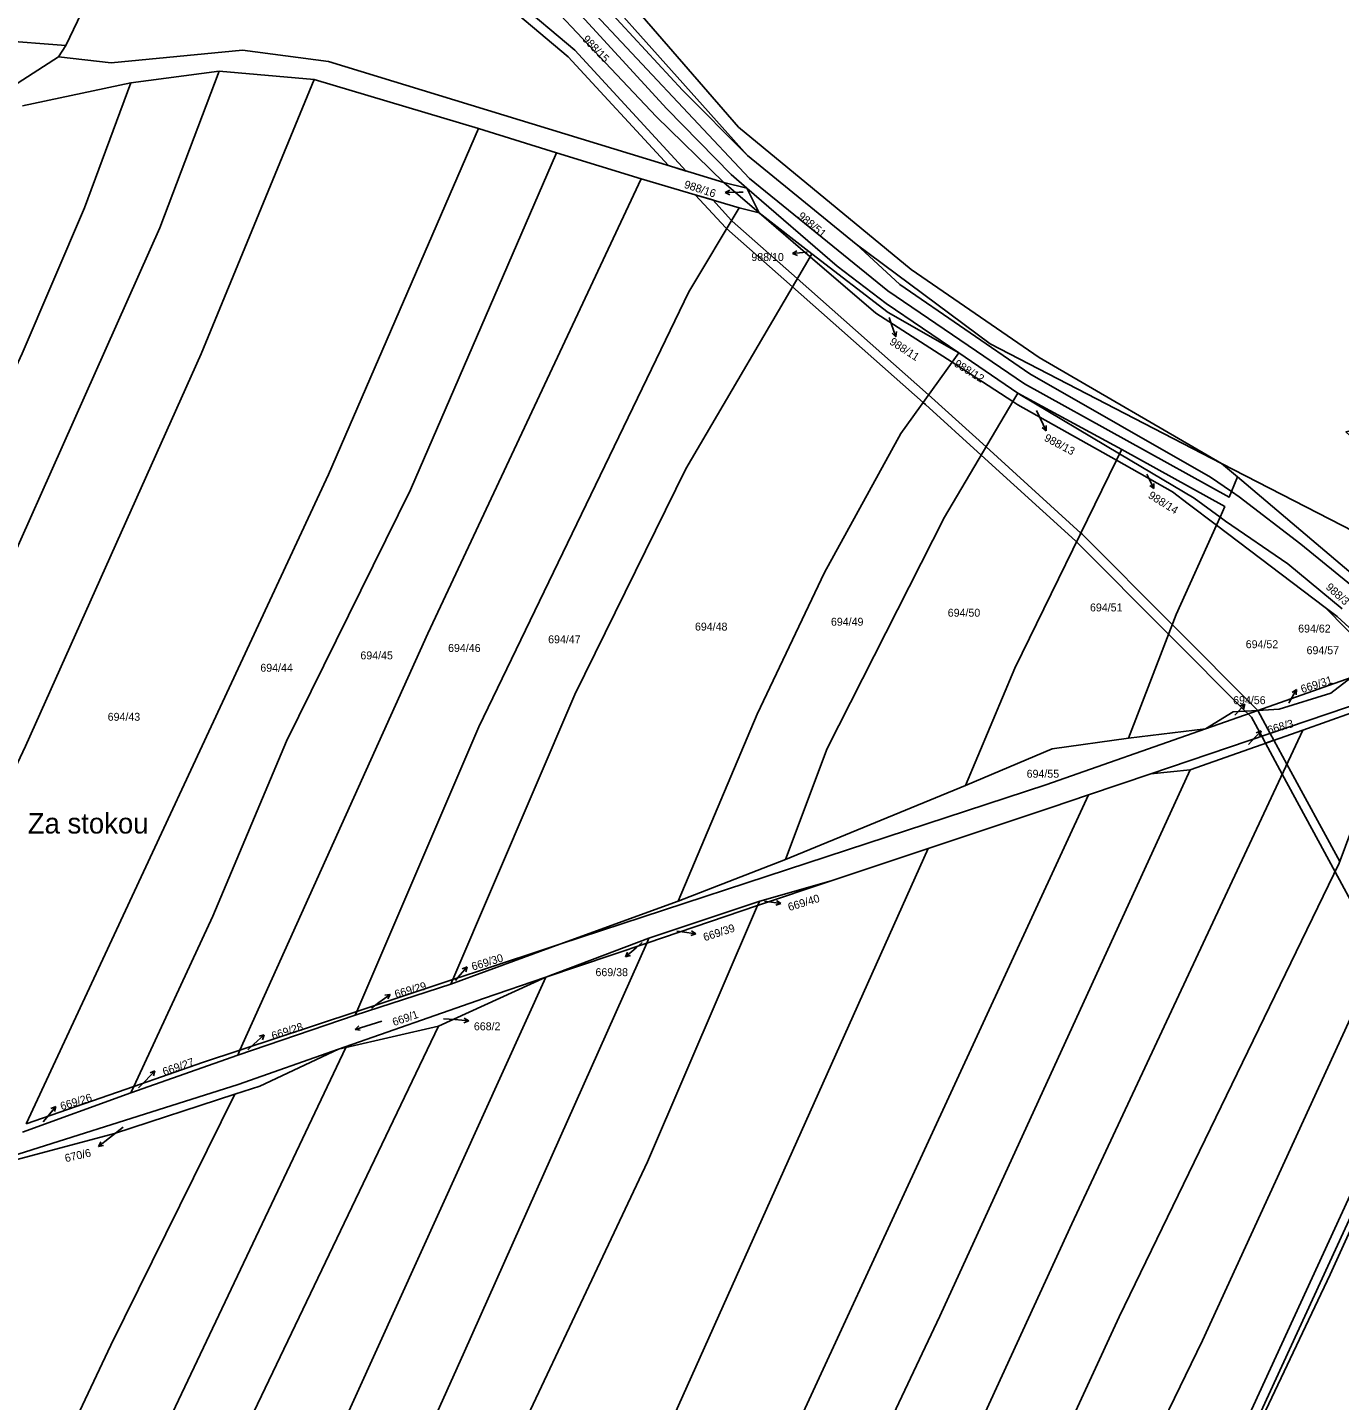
# Model space of a CAD drawing. Extents: x -757266 to -753360, y -1162585 to -1157740.
# Drawn here: x -755234 to -754953.1, y -1160665.3 to -1160371.4 of the extents above; entities that cross this region are included whole.
import ezdxf

# ---------------------------------------------------------------- set-up
doc = ezdxf.new("R2010")
doc.units = 0
for name, color, linetype in [('Hranice kat_území', 7, 'Continuous'), ('Hranice parcel', 7, 'Continuous'), ('Parcelní čísla', 7, 'Continuous'), ('Pop  PČ popisy', 7, 'Continuous'), ('Vnitřní kresba', 7, 'Continuous'), ('Věcná břemena k části', 7, 'Continuous'), ('Značky kultur', 7, 'Continuous')]:
    doc.layers.add(name, color=color, linetype=linetype)

msp = doc.modelspace()

# ---------------------------------------------------------------- linework, layer by layer
at = {"layer": 'Hranice kat_území'}
msp.add_lwpolyline([(-754836.68, -1160424.92), (-754843.51, -1160426.34), (-754867.82, -1160439.33), (-754951.71, -1160457.97), (-754910, -1160495.94), (-754907.43, -1160498.28), (-754905.04, -1160500.46), (-754900.14, -1160504.92), (-754937.1, -1160485.93), (-754978.36, -1160464.73), (-755017.36, -1160442.06), (-755044.83, -1160423.21), (-755081.79, -1160392.71), (-755127.23, -1160340.27), (-755153.29, -1160310.66), (-755189.84, -1160272.57)], dxfattribs=at)
at = {"layer": 'Hranice parcel'}
for p, q in [((-755225.78, -1160375.24), (-755214.23, -1160351.12)), ((-755225.78, -1160375.24), (-755408.03, -1160361.2)), ((-755227.31, -1160377.66), (-755225.78, -1160375.24)), ((-755192.92, -1160380.76), (-755211.82, -1160383.2)), ((-755172.6, -1160382.49), (-755192.92, -1160380.76)), ((-755211.82, -1160383.2), (-755235.06, -1160388.17)), ((-755137.45, -1160392.98), (-755172.6, -1160382.49)), ((-755120.74, -1160398.19), (-755137.45, -1160392.98)), ((-755102.58, -1160403.76), (-755120.74, -1160398.19)), ((-755079.81, -1160398.79), (-755056.55, -1160417.74)), ((-755081.62, -1160409.96), (-755102.58, -1160403.76)), ((-755084.87, -1160404.6), (-755079.94, -1160405.8)), ((-755084.87, -1160404.6), (-755077.36, -1160411.06)), ((-755077.36, -1160411.06), (-755079.94, -1160405.8)), ((-755077.36, -1160411.06), (-755081.62, -1160409.96)), ((-755077.36, -1160411.06), (-755066.09, -1160419.85)), ((-755066.44, -1160420.45), (-755077.36, -1160411.06)), ((-755066.44, -1160420.45), (-755066.09, -1160419.85)), ((-755034.6, -1160441.06), (-755036.04, -1160443.06)), ((-755021.95, -1160449.65), (-755034.6, -1160441.06)), ((-755036.04, -1160443.06), (-755023.01, -1160451.44)), ((-755023.01, -1160451.44), (-755021.95, -1160449.65)), ((-755021.95, -1160449.65), (-754999.73, -1160461.76)), ((-754978.36, -1160464.73), (-754974.95, -1160467.61)), ((-754979.45, -1160477.93), (-754956.2, -1160495.52)), ((-754947.13, -1160504.73), (-754956.2, -1160495.52)), ((-754950.61, -1160510.55), (-754970.61, -1160517.59)), ((-754947.42, -1160515.55), (-754993.5, -1160531.15)), ((-754970.61, -1160517.59), (-754981.79, -1160521.52)), ((-754998.29, -1160523.54), (-754981.79, -1160521.52)), ((-754985.1, -1160530.3), (-754960.96, -1160521.81)), ((-754993.5, -1160531.15), (-754985.1, -1160530.3)), ((-755071.71, -1160549.47), (-755033.18, -1160533.67)), ((-754993.5, -1160531.15), (-755006.85, -1160535.67)), ((-755041.15, -1160547.16), (-755061.89, -1160554.09)), ((-755094.69, -1160558.4), (-755071.71, -1160549.47)), ((-755061.89, -1160554.09), (-755077.67, -1160559.36)), ((-755077.16, -1160558.43), (-755061.89, -1160554.09)), ((-755120, -1160567.65), (-755094.69, -1160558.4)), ((-755077.67, -1160559.36), (-755101.37, -1160567.38)), ((-755100.92, -1160566.36), (-755077.16, -1160558.43)), ((-755077.67, -1160559.36), (-755077.16, -1160558.43)), ((-755120, -1160567.65), (-755143.33, -1160576.17)), ((-755123.03, -1160574.7), (-755100.92, -1160566.36)), ((-755101.37, -1160567.38), (-755123.03, -1160574.7)), ((-755101.37, -1160567.38), (-755100.92, -1160566.36)), ((-755146, -1160585.19), (-755123.03, -1160574.7)), ((-755143.33, -1160576.17), (-755163.81, -1160582.84)), ((-755142.91, -1160575.19), (-755163.45, -1160582.01)), ((-755143.33, -1160576.17), (-755142.91, -1160575.19)), ((-755163.81, -1160582.84), (-755188.97, -1160591.37)), ((-755163.45, -1160582.01), (-755188.5, -1160590.32)), ((-755163.81, -1160582.84), (-755163.45, -1160582.01)), ((-755165.8, -1160589.74), (-755146, -1160585.19)), ((-755167.41, -1160590.11), (-755165.8, -1160589.74)), ((-755188.97, -1160591.37), (-755211.87, -1160599.47)), ((-755188.97, -1160591.37), (-755188.5, -1160590.32)), ((-755211.23, -1160598.09), (-755234.24, -1160606.08)), ((-755211.87, -1160599.47), (-755211.23, -1160598.09)), ((-755211.87, -1160599.47), (-755235.07, -1160607.86))]:
    msp.add_line(p, q, dxfattribs=at)
for points in [[(-754978.36, -1160464.73), (-755017.36, -1160442.06), (-755044.83, -1160423.21), (-755081.79, -1160392.71), (-755127.23, -1160340.27), (-755153.29, -1160310.66), (-755189.84, -1160272.57), (-755198.61, -1160264.22)], [(-755179.02, -1160301.66), (-755140.77, -1160333.66), (-755129.85, -1160342.79), (-755079.81, -1160398.79)], [(-754974.95, -1160467.61), (-754976.22, -1160470.75), (-754976.7, -1160471.93), (-755020.51, -1160447.64), (-755049.76, -1160427.78), (-755079.39, -1160403.71), (-755139.72, -1160339.43), (-755150.98, -1160330.64), (-755160.64, -1160323.09)], [(-755079.94, -1160405.8), (-755083.32, -1160402.88), (-755097.07, -1160388.79), (-755134.5, -1160347.95), (-755136.84, -1160350.67)], [(-755136.84, -1160350.67), (-755099.4, -1160390.46), (-755084.87, -1160404.6)], [(-755408.03, -1160361.2), (-755410.88, -1160362.74), (-755447.95, -1160377.88), (-755452.11, -1160383.8), (-755423.38, -1160389.29), (-755390.71, -1160391.7), (-755352.32, -1160391.92), (-755317.01, -1160388.19), (-755277.97, -1160387.97), (-755237.18, -1160384.02), (-755227.31, -1160377.66)], [(-755227.31, -1160377.66), (-755216.08, -1160378.97), (-755187.92, -1160376.23), (-755169.51, -1160378.66), (-755084.87, -1160404.6)], [(-755302.8, -1160627.98), (-755258.75, -1160533.19), (-755205.63, -1160414.29), (-755192.92, -1160380.76)], [(-755322.45, -1160633.68), (-755269.46, -1160515.52), (-755235.11, -1160441.19), (-755221.8, -1160410.02), (-755211.82, -1160383.2)], [(-755279.36, -1160620.71), (-755234.42, -1160525.24), (-755196.79, -1160441.23), (-755172.6, -1160382.49)], [(-755234.24, -1160606.08), (-755169.52, -1160467.09), (-755137.45, -1160392.98)], [(-755211.23, -1160598.09), (-755194.26, -1160561.64), (-755178.49, -1160524.16), (-755152.01, -1160470.33), (-755120.74, -1160398.19)], [(-755188.5, -1160590.32), (-755148.28, -1160501.09), (-755102.58, -1160403.76)], [(-755163.45, -1160582.01), (-755137.33, -1160521.1), (-755092.39, -1160427.99), (-755081.62, -1160409.96)], [(-755056.55, -1160417.74), (-755027.91, -1160439.08), (-754978.36, -1160464.73)], [(-755142.91, -1160575.19), (-755116.78, -1160514.16), (-755093.04, -1160465.87), (-755066.44, -1160420.45)], [(-755036.04, -1160443.06), (-755052.36, -1160432.55), (-755066.44, -1160420.45)], [(-755066.09, -1160419.85), (-755049.71, -1160432.37), (-755034.6, -1160441.06)], [(-755094.69, -1160558.4), (-755077.77, -1160518.41), (-755063.34, -1160488.04), (-755047.02, -1160458.28), (-755036.04, -1160443.06)], [(-755071.71, -1160549.47), (-755062.75, -1160525.7), (-755037.69, -1160476.19), (-755023.01, -1160451.44)], [(-755000.84, -1160464.02), (-755021.93, -1160452.14), (-755023.01, -1160451.44)], [(-755000.84, -1160464.02), (-755000.17, -1160462.65), (-754999.73, -1160461.76)], [(-754999.73, -1160461.76), (-754977.67, -1160473.96), (-754978.66, -1160476.18), (-754979.45, -1160477.93)], [(-755033.18, -1160533.67), (-755022.57, -1160508.57), (-755000.84, -1160464.02)], [(-754979.45, -1160477.93), (-754985.47, -1160473.37), (-754988.88, -1160470.76), (-755000.84, -1160464.02)], [(-754978.36, -1160464.73), (-754937.1, -1160485.93), (-754900.14, -1160504.92)], [(-754915.94, -1160516.47), (-754933.41, -1160503.58), (-754939.41, -1160497.69), (-754974.95, -1160467.61)], [(-754998.29, -1160523.54), (-754988.03, -1160497.04), (-754979.45, -1160477.93)], [(-754956.2, -1160495.52), (-754953.61, -1160497.48), (-754946.67, -1160503.85)], [(-755239.59, -1161188.33), (-755189.22, -1161066.1), (-755124.51, -1160919.12), (-755055.31, -1160766.7), (-755000.26, -1160647.4), (-754953.16, -1160550.31), (-754939.15, -1160512.75)], [(-754950.61, -1160510.55), (-754954.92, -1160513.92), (-754966.03, -1160517.34), (-754970.61, -1160517.59)], [(-754960.96, -1160521.81), (-754950.51, -1160518.13), (-754947.42, -1160515.55)], [(-754981.79, -1160521.52), (-754975.86, -1160517.87), (-754970.61, -1160517.59)], [(-755258.72, -1161181.18), (-755209.68, -1161068.68), (-755144.04, -1160922.19), (-755126.15, -1160879.45), (-755010.42, -1160627.49), (-754960.96, -1160521.81)], [(-754981.79, -1160521.52), (-755015.96, -1160533.54), (-755075.64, -1160553.07), (-755120, -1160567.65)], [(-755033.18, -1160533.67), (-755014.63, -1160525.78), (-754998.29, -1160523.54)], [(-755275.71, -1161173.74), (-755223.74, -1161057.26), (-755180.23, -1160958.74), (-755117.97, -1160820.72), (-755099.93, -1160776.84), (-755038.69, -1160647.24), (-754985.1, -1160530.3)], [(-755223.83, -1161194.14), (-755155.09, -1161030.95), (-755113.4, -1160935.38), (-755035.3, -1160761.37), (-754982.41, -1160652.48), (-754927.53, -1160532.91)], [(-755292.32, -1161165.4), (-755230.27, -1161030.46), (-755190.55, -1160934.6), (-755105.63, -1160749.58), (-755006.85, -1160535.67)], [(-755006.85, -1160535.67), (-755014.8, -1160538.36), (-755041.15, -1160547.16)], [(-755315.27, -1161153.68), (-755261.54, -1161031.78), (-755192.14, -1160879.45), (-755179.27, -1160847.36), (-755151.78, -1160790.14), (-755102.03, -1160682.93), (-755041.15, -1160547.16)], [(-755338.88, -1161141.19), (-755323.15, -1161100.32), (-755246.88, -1160934.52), (-755180.17, -1160786.32), (-755141.87, -1160700.25), (-755101.27, -1160614.23), (-755077.67, -1160559.36)], [(-755206.94, -1161200.05), (-755159.46, -1161085.95), (-755113.5, -1160980.32), (-755087.61, -1160917.94), (-755037.27, -1160811.67), (-754955.13, -1160638.32), (-754918.81, -1160558.44)], [(-755354.3, -1161132.73), (-755324.81, -1161064.13), (-755286.33, -1160980.6), (-755237.8, -1160874.55), (-755191.07, -1160767.63), (-755140.44, -1160654.8), (-755101.37, -1160567.38)], [(-755120, -1160567.65), (-755137.66, -1160573.45), (-755142.91, -1160575.19)], [(-755369.72, -1161124.77), (-755347.72, -1161071.88), (-755254.08, -1160863.01), (-755172.9, -1160684.55), (-755123.03, -1160574.7)], [(-755123.03, -1160574.7), (-755136.32, -1160579.23), (-755167.41, -1160590.11)], [(-755386.21, -1161118.44), (-755354.46, -1161042.9), (-755317.33, -1160958.88), (-755238.34, -1160786.92), (-755185.55, -1160667.77), (-755146, -1160585.19)], [(-755401.23, -1161112.85), (-755369.98, -1161038.68), (-755317.2, -1160921.35), (-755260.72, -1160793.9), (-755215.57, -1160694.59), (-755165.8, -1160589.74)], [(-755317.46, -1160638.78), (-755250.21, -1160617.08), (-755188.9, -1160597.63), (-755167.41, -1160590.11)], [(-755188.5, -1160590.32), (-755196.47, -1160592.97), (-755211.23, -1160598.09)], [(-755167.41, -1160590.11), (-755184.25, -1160598), (-755189.61, -1160599.75)], [(-755419.99, -1161106.75), (-755378.63, -1161012.83), (-755329.09, -1160900.22), (-755295.38, -1160824.05), (-755243.53, -1160711.37), (-755216.16, -1160653.5), (-755189.61, -1160599.75)], [(-755189.61, -1160599.75), (-755215.32, -1160608.12), (-755237.57, -1160614.05)]]:
    msp.add_lwpolyline(points, dxfattribs=at)
at = {"layer": 'Pop  PČ popisy'}
for p, q in [((-755084.591, -1160406.702), (-755083.598, -1160406.184)), ((-755081.59, -1160406.65), (-755084.591, -1160406.702)), ((-755084.591, -1160406.702), (-755083.58, -1160407.186)), ((-755080.78, -1160406.64), (-755081.59, -1160406.65)), ((-755070.195, -1160419.774), (-755069.251, -1160419.171)), ((-755067.21, -1160419.46), (-755070.195, -1160419.774)), ((-755070.195, -1160419.774), (-755069.146, -1160420.167)), ((-755067.09, -1160419.45), (-755067.21, -1160419.46)), ((-755049.5, -1160433.47), (-755049.06, -1160434.77)), ((-755049.06, -1160434.77), (-755048.083, -1160437.607)), ((-755048.083, -1160437.607), (-755048.882, -1160436.824)), ((-755048.083, -1160437.607), (-755047.936, -1160436.498)), ((-755017.98, -1160453.39), (-755017.19, -1160455.03)), ((-755017.19, -1160455.03), (-755015.874, -1160457.727)), ((-755015.874, -1160457.727), (-755016.764, -1160457.047)), ((-755015.874, -1160457.727), (-755015.863, -1160456.608)), ((-754994.33, -1160467.01), (-754994.14, -1160467.41)), ((-754994.14, -1160467.41), (-754992.824, -1160470.107)), ((-754992.824, -1160470.107), (-754992.813, -1160468.988)), ((-754992.824, -1160470.107), (-754993.714, -1160469.427)), ((-754963.78, -1160515.72), (-754962.325, -1160513.095)), ((-754962.325, -1160513.095), (-754963.249, -1160513.728)), ((-754962.325, -1160513.095), (-754962.373, -1160514.214)), ((-754975.38, -1160518.44), (-754973.333, -1160516.245)), ((-754973.333, -1160516.245), (-754974.383, -1160516.636)), ((-754973.333, -1160516.245), (-754973.65, -1160517.319)), ((-754963.97, -1160516.06), (-754963.78, -1160515.72)), ((-754975.53, -1160518.6), (-754975.38, -1160518.44)), ((-754971.92, -1160524.17), (-754969.873, -1160521.975)), ((-754969.873, -1160521.975), (-754970.923, -1160522.366)), ((-754969.873, -1160521.975), (-754970.19, -1160523.049)), ((-754972.55, -1160524.86), (-754971.92, -1160524.17)), ((-755076.19, -1160558.42), (-755075.68, -1160558.49)), ((-755075.68, -1160558.49), (-755072.708, -1160558.908)), ((-755072.708, -1160558.908), (-755073.77, -1160559.264)), ((-755072.708, -1160558.908), (-755073.63, -1160558.272)), ((-755094.99, -1160564.81), (-755093.84, -1160564.96)), ((-755093.84, -1160564.96), (-755090.868, -1160565.378)), ((-755090.868, -1160565.378), (-755091.93, -1160565.734)), ((-755090.868, -1160565.378), (-755091.79, -1160564.742)), ((-755103.69, -1160568.39), (-755105.955, -1160570.359)), ((-755102.39, -1160567.28), (-755103.69, -1160568.39)), ((-755105.955, -1160570.359), (-755105.528, -1160569.324)), ((-755105.955, -1160570.359), (-755104.871, -1160570.08)), ((-755142.34, -1160575.4), (-755141.81, -1160574.77)), ((-755141.81, -1160574.77), (-755139.881, -1160572.471)), ((-755139.881, -1160572.471), (-755140.908, -1160572.916)), ((-755139.881, -1160572.471), (-755140.141, -1160573.56)), ((-755160.36, -1160581.29), (-755158.77, -1160580.13)), ((-755158.77, -1160580.13), (-755156.342, -1160578.366)), ((-755156.342, -1160578.366), (-755157.447, -1160578.55)), ((-755156.342, -1160578.366), (-755156.858, -1160579.36)), ((-755144.89, -1160583.58), (-755142.49, -1160583.78)), ((-755142.49, -1160583.78), (-755139.5, -1160584.042)), ((-755139.5, -1160584.042), (-755140.454, -1160583.455)), ((-755139.5, -1160584.042), (-755140.542, -1160584.453)), ((-755186.81, -1160590.24), (-755185.5, -1160589.04)), ((-755185.5, -1160589.04), (-755183.27, -1160587.032)), ((-755183.27, -1160587.032), (-755184.349, -1160587.33)), ((-755183.27, -1160587.032), (-755183.679, -1160588.074)), ((-755208.77, -1160596.92), (-755206.685, -1160594.761)), ((-755206.685, -1160594.761), (-755207.741, -1160595.134)), ((-755206.685, -1160594.761), (-755207.021, -1160595.83)), ((-755210.18, -1160598.38), (-755208.77, -1160596.92)), ((-755229.81, -1160604.7), (-755227.921, -1160602.368)), ((-755227.921, -1160602.368), (-755228.941, -1160602.831)), ((-755227.921, -1160602.368), (-755228.163, -1160603.461)), ((-755230.59, -1160605.65), (-755229.81, -1160604.7)), ((-755213.49, -1160606.78), (-755216.42, -1160609.07)), ((-755216.42, -1160609.07), (-755218.785, -1160610.918)), ((-755218.785, -1160610.918), (-755218.304, -1160609.906)), ((-755218.785, -1160610.918), (-755217.687, -1160610.696))]:
    msp.add_line(p, q, dxfattribs=at)
at = {"layer": 'Vnitřní kresba'}
for p, q in [((-755130.79, -1160344.63), (-755093.74, -1160384.82)), ((-755093.74, -1160384.82), (-755079.81, -1160398.79)), ((-755060.66, -1160422.45), (-755079.94, -1160405.8)), ((-755056.55, -1160417.74), (-755047.21, -1160426.38)), ((-755050.16, -1160430.48), (-755060.66, -1160422.45)), ((-755047.21, -1160426.38), (-755019.42, -1160445.52)), ((-755034.6, -1160441.06), (-755050.16, -1160430.48)), ((-755019.42, -1160445.52), (-754980.73, -1160467.68)), ((-755021.51, -1160449.95), (-755021.95, -1160449.65)), ((-755000.17, -1160462.65), (-755021.51, -1160449.95)), ((-754984.24, -1160472.12), (-755000.17, -1160462.65)), ((-754980.73, -1160467.68), (-754976.22, -1160470.75)), ((-754978.66, -1160476.18), (-754984.24, -1160472.12)), ((-754976.22, -1160470.75), (-754974.56, -1160471.88)), ((-754974.56, -1160471.88), (-754961.36, -1160482.02)), ((-754977.48, -1160477.04), (-754978.66, -1160476.18)), ((-754964.13, -1160486.19), (-754977.48, -1160477.04)), ((-754961.36, -1160482.02), (-754949.4, -1160491.8)), ((-754952.52, -1160495.81), (-754964.13, -1160486.19))]:
    msp.add_line(p, q, dxfattribs=at)
at = {"layer": 'Věcná břemena k části'}
for points in [[(-755195.4, -1160311.33), (-755196.26, -1160313.16), (-755190.97, -1160315.08), (-755156.86, -1160345.1), (-755118.2, -1160377.68), (-755096.76, -1160400.96), (-755092.96, -1160402.12), (-755116.82, -1160376.24), (-755155.54, -1160343.6), (-755189.93, -1160313.32)], [(-754970.61, -1160517.59), (-754988.88, -1160499.24), (-755008.21, -1160479.83), (-755008.45, -1160479.62), (-755028.77, -1160461.16), (-755040.44, -1160450.56), (-755041.06, -1160450.01), (-755069.18, -1160425.13), (-755083.1, -1160412.82), (-755083.24, -1160412.67), (-755087.28, -1160408.29), (-755091.02, -1160407.18), (-755084.5, -1160414.26), (-755084.3, -1160414.44), (-755070.21, -1160426.89), (-755042.23, -1160451.64), (-755041.76, -1160452.06), (-755029.81, -1160462.91), (-755009.63, -1160481.25), (-755009.37, -1160481.51), (-754989.67, -1160501.27), (-754973.26, -1160517.73)], [(-754973.26, -1160517.73), (-754972.67, -1160518.32), (-754971.95, -1160519.04), (-754969.75, -1160523.11), (-754968.93, -1160524.61), (-754967.14, -1160523.98), (-754967.94, -1160522.5), (-754970.61, -1160517.59)]]:
    msp.add_lwpolyline(points, close=True, dxfattribs=at)
for points in [[(-754953.03, -1160549.95), (-754964.36, -1160529.09), (-754967.14, -1160523.98), (-754968.93, -1160524.61), (-754965.36, -1160531.21), (-754954.04, -1160552.13), (-754944.47, -1160569.82)], [(-754947.6, -1160614.34), (-754989.36, -1160705.23), (-755074.67, -1160886.43), (-755095.68, -1160932.81), (-755115.67, -1160978.26), (-755155.39, -1161070.65), (-755194.27, -1161163.35), (-755209.61, -1161199.14), (-755210.9, -1161202.14), (-755209.05, -1161202.89), (-755207.72, -1161199.78), (-755192.43, -1161164.13), (-755153.55, -1161071.43), (-755113.85, -1160979.08), (-755098.62, -1160944.47), (-755087.61, -1160917.94), (-755037.27, -1160811.67), (-755036.41, -1160809.85), (-754987.54, -1160706.06), (-754945.78, -1160615.18)]]:
    msp.add_lwpolyline(points, dxfattribs=at)
at = {"layer": 'Značky kultur'}
for p, q in [((-755158.11, -1160584.12), (-755163.848, -1160585.874)), ((-755163.848, -1160585.874), (-755163.06, -1160585.109)), ((-755163.848, -1160585.874), (-755162.767, -1160586.068))]:
    msp.add_line(p, q, dxfattribs=at)

# ---------------------------------------------------------------- texts
at = {"layer": 'Parcelní čísla'}
for s, rotation, p in [('988/15', 313.999997, (-755115.301, -1160374.03)), ('988/16', 342, (-755093.551, -1160405.668)), ('988/51', 320, (-755069.206, -1160412.011)), ('988/11', 327, (-755049.573, -1160439.069)), ('988/12', 328, (-755035.74, -1160443.79)), ('988/13', 332, (-755016.478, -1160459.758)), ('988/14', 328, (-754994.205, -1160471.972)), ('988/3', 318, (-754956.168, -1160491.401)), ('669/31', 18, (-754961.077, -1160513.898)), ('668/3', 16, (-754968.265, -1160522.667)), ('669/40', 17, (-755070.877, -1160560.554)), ('669/39', 18, (-755088.989, -1160567.009)), ('669/30', 17, (-755138.621, -1160573.292)), ('669/29', 16, (-755155.105, -1160579.187)), ('669/1', 19, (-755155.513, -1160585.183)), ('669/28', 18, (-755181.417, -1160588.128)), ('669/27', 19, (-755204.713, -1160595.803)), ('669/26', 17, (-755226.661, -1160603.192)), ('670/6', 13, (-755225.777, -1160614.309))]:
    msp.add_text(s, height=1.7, rotation=rotation, dxfattribs=at).set_placement(p)
for s, p in [('988/10', (-755079.005, -1160421.37)), ('694/51', (-755006.51, -1160496.39)), ('694/49', (-755061.97, -1160499.45)), ('694/50', (-755036.96, -1160497.52)), ('694/47', (-755122.51, -1160503.21)), ('694/48', (-755091.08, -1160500.49)), ('694/62', (-754961.945, -1160500.91)), ('694/46', (-755143.93, -1160505.06)), ('694/52', (-754973.17, -1160504.26)), ('694/57', (-754960.145, -1160505.55)), ('694/45', (-755162.7, -1160506.65)), ('694/44', (-755184.12, -1160509.3)), ('694/56', (-754975.87, -1160516.24)), ('694/43', (-755216.8, -1160519.8)), ('694/55', (-755020.07, -1160531.99)), ('669/38', (-755112.375, -1160574.468)), ('668/2', (-755138.41, -1160586.058))]:
    msp.add_text(s, height=1.7, dxfattribs=at).set_placement(p)
at = {"layer": 'Pop  PČ popisy'}
msp.add_text('Za stokou', height=4.4, dxfattribs=at).set_placement((-755233.9, -1160543.94))

doc.saveas('drawing.dxf')
